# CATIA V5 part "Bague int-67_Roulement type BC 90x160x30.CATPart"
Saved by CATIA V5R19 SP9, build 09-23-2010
Part number: Bague int-67_Roulement type BC 90x160x30
Revision: ANY
Definition: UNKNOWN
Nomenclature: Bague int-67_Roulement type BC 90x160x30
Source: Unknown
Bounding box of the stored display mesh (mm): x -15 to 15, y -56.39 to 56.39, z -56.583 to 56.583
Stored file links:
  Y:\fin de projet cabestan poupee\Bague int-67_Roulement type BC 90x160x30.CATPart
  Ass_arbre poupee_1.CATProduct
  Y:\bricolage cabestan\6_axe.CATPart
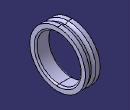
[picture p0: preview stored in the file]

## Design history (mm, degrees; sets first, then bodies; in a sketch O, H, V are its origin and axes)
Body1 "NONE" (main body)
  Solid1: solid without history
